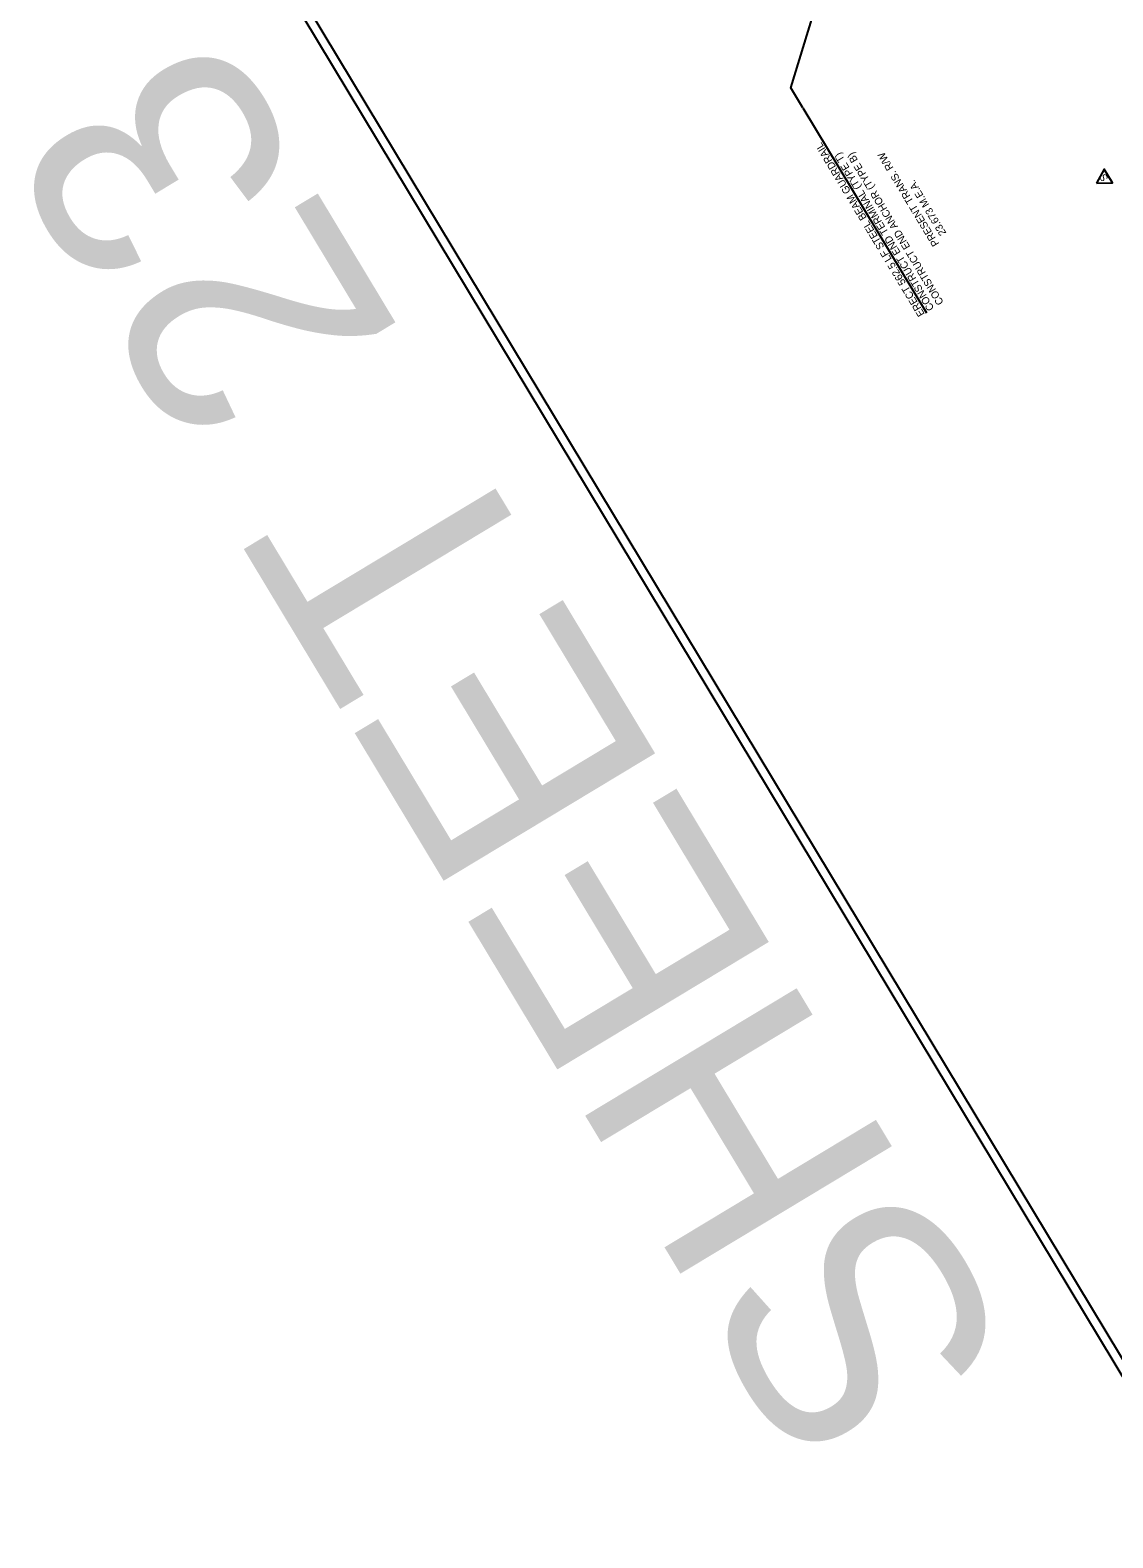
# Model space of a CAD drawing. Extents: x 1613170 to 1614989, y 1084261 to 1086549.
# Drawn here: x 1613170 to 1614047, y 1084261 to 1085483 of the extents above; entities that cross this region are included whole.
import ezdxf

# ---------------------------------------------------------------- set-up
doc = ezdxf.new("R2010")
doc.units = 0
for name, color, linetype in [('Level 11', 7, 'Continuous'), ('Level 17', 7, 'Continuous'), ('Level 19', 7, 'Continuous'), ('Level 26', 7, 'Continuous'), ('Level 4', 7, 'Continuous'), ('Level 8', 7, 'Continuous')]:
    doc.layers.add(name, color=color, linetype=linetype)

msp = doc.modelspace()

# ---------------------------------------------------------------- linework, layer by layer
at = {"layer": 'Level 17'}
msp.add_lwpolyline([(1614088.5, 1084350.8), (1613395.8, 1085500.1), (1613423.8, 1085516.9), (1613343.7, 1085653.3), (1614126.4, 1086125), (1614900.7, 1084840.3)], close=True, dxfattribs=at)
msp.add_lwpolyline([(1614088.5, 1084350.8), (1613395.8, 1085500.1), (1613423.8, 1085516.9), (1613343.7, 1085653.3), (1614126.4, 1086125), (1614900.7, 1084840.3)], close=True, dxfattribs=at)
msp.add_lwpolyline([(1614088.5, 1084350.8), (1613395.8, 1085500.1), (1613423.8, 1085516.9), (1613343.7, 1085653.3), (1614126.4, 1086125), (1614900.7, 1084840.3)], close=True, dxfattribs=at)
at = {"layer": 'Level 26'}
msp.add_line((1613796.3, 1085419.7), (1613896.4, 1085253.6), dxfattribs=at)
msp.add_lwpolyline([(1613796.3, 1085419.7), (1613786.5, 1085435.8), (1613824.4, 1085560.6)], dxfattribs=at)
at = {"layer": 'Level 4'}
msp.add_lwpolyline([(1614134, 1084261.5), (1613269.4, 1085696.1), (1614088.6, 1086189.8), (1614953.2, 1084755.2)], close=True, dxfattribs=at)
at = {"layer": 'Level 8'}
msp.add_lwpolyline([(1614034.1, 1085358.6), (1614047.1, 1085358.8), (1614040.4, 1085370)], close=True, dxfattribs=at)

# ---------------------------------------------------------------- texts
at = {"layer": 'Level 11'}
for s, p in [('PRESENT TRANS. R/W ', (1613906.8, 1085309.6)), ('  23.673 M.E.A.', (1613914.9, 1085314.5))]:
    msp.add_text(s, height=6, rotation=121.0768, dxfattribs=at).set_placement(p)
at = {"layer": 'Level 19'}
msp.add_text('SHEET 23', height=200, rotation=121.0768, dxfattribs=at).set_placement((1613971.7, 1084407.1))
at = {"layer": 'Level 26'}
for s, p in [('ERECT 562.5 LF STEEL BEAM GUARDRAIL', (1613895.1, 1085252.8)), ('CONSTRUCT END TERMINAL (TYPE T)', (1613902.8, 1085257.4)), ('CONSTRUCT END ANCHOR (TYPE B)', (1613910.5, 1085262.1))]:
    msp.add_text(s, height=6, rotation=121.0784, dxfattribs=at).set_placement(p)
at = {"layer": 'Level 8'}
msp.add_text('S', height=6, rotation=121.0768, dxfattribs=at).set_placement((1614043.9, 1085362.3))

doc.saveas('drawing.dxf')
